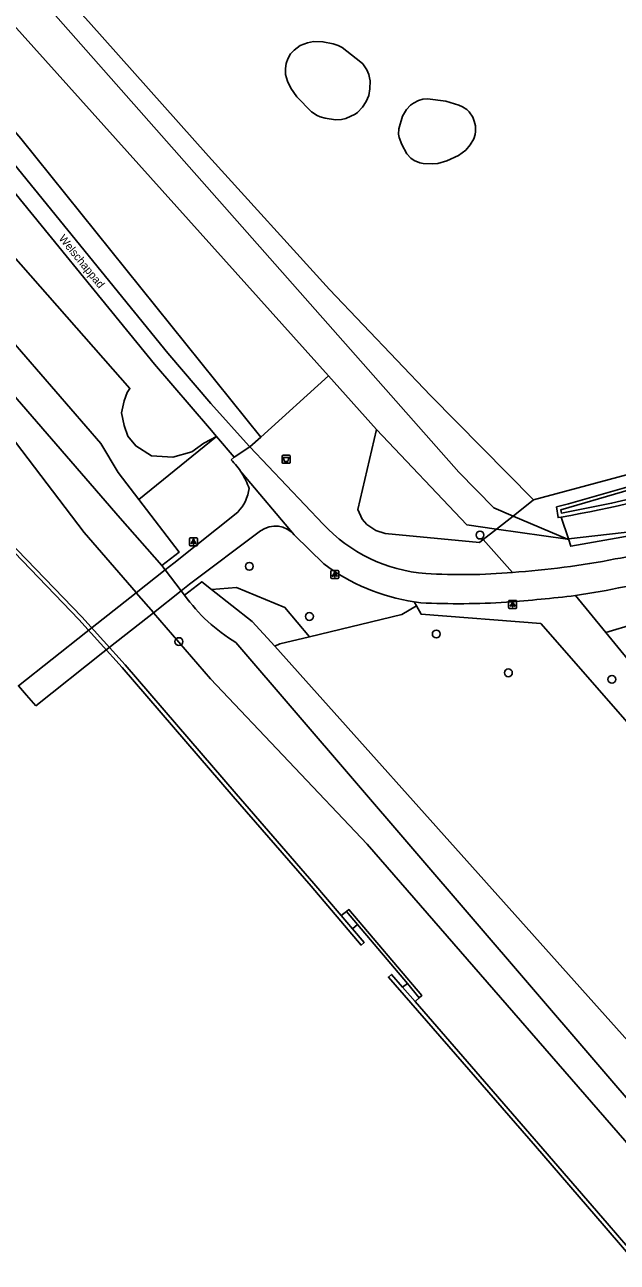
# Model space of a CAD drawing. Extents: x 156061 to 157804, y 383451 to 385640.
# Drawn here: x 157335.7 to 157409.7, y 383817.8 to 383972.4 of the extents above; entities that cross this region are included whole.
import ezdxf

# ---------------------------------------------------------------- set-up
doc = ezdxf.new("R2010")
doc.units = 0
for name, color, linetype in [('IMGEO_Afvalbak', 7, 'Continuous'), ('IMGEO_Berm_groen', 7, 'Continuous'), ('IMGEO_Boom', 7, 'Continuous'), ('IMGEO_Dek', 7, 'Continuous'), ('IMGEO_Fietspad_gesloten', 7, 'Continuous'), ('IMGEO_Fietspad_halfverhard', 7, 'Continuous'), ('IMGEO_Gemengd_bos', 7, 'Continuous'), ('IMGEO_Grasland_overig', 7, 'Continuous'), ('IMGEO_Groenvoorziening', 7, 'Continuous'), ('IMGEO_Hek', 7, 'Continuous'), ('IMGEO_Kademuur', 7, 'Continuous'), ('IMGEO_Lichtpunt', 7, 'Continuous'), ('IMGEO_Loofbos', 7, 'Continuous'), ('IMGEO_Openbare_ruimte_label', 7, 'Continuous'), ('IMGEO_Waterloop', 7, 'Continuous')]:
    doc.layers.add(name, color=color, linetype=linetype)

msp = doc.modelspace()

# ---------------------------------------------------------------- linework, layer by layer
at = {"layer": 'IMGEO_Afvalbak'}
for p, q in [((157367.87, 383917.72), (157367.87, 383918.52)), ((157367.87, 383918.52), (157367.87, 383917.72)), ((157367.97, 383918.62), (157368.76, 383918.62)), ((157368.76, 383918.62), (157367.97, 383918.62)), ((157368.76, 383917.62), (157367.97, 383917.62)), ((157367.97, 383917.62), (157368.76, 383917.62)), ((157368.86, 383918.52), (157368.86, 383917.72)), ((157368.86, 383917.72), (157368.86, 383918.52))]:
    msp.add_line(p, q, dxfattribs=at)
msp.add_lwpolyline([(157368.01, 383918.34), (157368.72, 383918.34), (157368.57, 383917.86), (157368.16, 383917.86), (157368.01, 383918.34)], dxfattribs=at)
for centre, start, end in [((157367.97, 383918.52), 90, 180), ((157367.97, 383918.52), 90, 180), ((157367.97, 383917.72), 180, 270), ((157367.97, 383917.72), 180, 270), ((157368.76, 383918.52), 0, 90), ((157368.76, 383918.52), 360, 90), ((157368.76, 383917.72), 270, 0), ((157368.76, 383917.72), 270, 0)]:
    msp.add_arc(centre, 0.1, start, end, dxfattribs=at)
at = {"layer": 'IMGEO_Berm_groen'}
for points in [[(157359.67, 383920.98), (157358.1, 383920.12), (157356.58, 383919.05), (157354.21, 383918.37), (157351.57, 383918.55), (157349.58, 383919.8), (157348.59, 383921.01), (157348.13, 383922.34), (157347.8, 383923.91), (157348.15, 383925.44), (157348.5, 383926.48), (157348.86, 383926.97), (157290.11, 383993.81)], [(157404.49, 383901.1), (157408.28, 383896.48)], [(157408.28, 383896.48), (157411.9, 383897.54)]]:
    msp.add_lwpolyline(points, dxfattribs=at)
at = {"layer": 'IMGEO_Boom'}
for centre in [(157392.58, 383908.65), (157363.77, 383904.75), (157371.28, 383898.48), (157387.12, 383896.29), (157354.98, 383895.34), (157396.13, 383891.44), (157409.05, 383890.62)]:
    msp.add_circle(centre, 0.489, dxfattribs=at)
at = {"layer": 'IMGEO_Dek'}
msp.add_lwpolyline([(157337.1, 383887.33), (157345.5, 383893.97), (157351.81, 383898.95), (157355.26, 383901.69), (157353.28, 383904.31), (157349.65, 383901.45), (157343.34, 383896.46), (157334.93, 383889.83), (157335.95, 383888.66)], close=True, dxfattribs=at)
at = {"layer": 'IMGEO_Fietspad_gesloten'}
for points in [[(157361.89, 383918.4), (157363.83, 383919.68)], [(157372.99, 383910.03), (157363.83, 383919.68)], [(157361.89, 383918.4), (157361.49, 383918.05)], [(157362.83, 383916.41), (157369.39, 383908.68), (157369.41, 383908.65)], [(157362.33, 383911.52), (157354.33, 383905.13), (157353.28, 383904.31)], [(157355.26, 383901.69), (157356.3, 383902.51), (157365.18, 383909.17)], [(157369.41, 383908.65), (157373.09, 383905.05)], [(157353.28, 383904.31), (157355.26, 383901.69)], [(157384.36, 383900.3), (157385.21, 383900.19)]]:
    msp.add_lwpolyline(points, dxfattribs=at)
for centre, radius, start, end in [((157355.53, 383911.82), 8.62, 32.1357, 46.2952), ((157355.49, 383911.78), 8.68, 18.1348, 32.1986), ((157358.6, 383915.12), 5.18, 316.0682, 352.9886), ((157387.3, 383923.33), 19.54, 222.8896, 265.5902), ((157367.02, 383906.68), 3.09, 39.3452, 126.5048), ((157395.45, 383986.55), 82.09, 279.8246, 287.2036), ((157389.64, 384006.87), 103.13, 273.892, 281.0783), ((157388.1, 383924.92), 24.9, 232.922, 261.3694), ((157390.32, 383981.53), 77.82, 266.6717, 274.6602), ((157386.75, 384018.34), 118.58, 278.604, 284.6469), ((157383.21, 384078.23), 178.41, 274.0796, 276.8514), ((157389.88, 383988.67), 88.6, 266.974, 273.894)]:
    msp.add_arc(centre, radius, start, end, dxfattribs=at)
at = {"layer": 'IMGEO_Fietspad_halfverhard'}
for points in [[(157237.28, 384056.66), (157244.45, 384048.49), (157247.83, 384044.71), (157258.97, 384032.48), (157270.57, 384020.69), (157270.96, 384020.29), (157290.75, 384000.1), (157290.84, 384000), (157295.59, 383994.9), (157306.48, 383982.75), (157317.9, 383970.66), (157322.77, 383965.41), (157327.3, 383960.08), (157331.11, 383955.48), (157351.93, 383929.99), (157358.8, 383922.02), (157359.67, 383920.98)], [(157363.83, 383919.68), (157363.76, 383919.76), (157358.97, 383925.08), (157353.6, 383931.38), (157332.79, 383957.01), (157329.26, 383961.31)], [(157359.67, 383920.98), (157361.89, 383918.4)]]:
    msp.add_lwpolyline(points, dxfattribs=at)
at = {"layer": 'IMGEO_Gemengd_bos'}
for points in [[(157359.67, 383920.98), (157349.99, 383913.1)], [(157352.86, 383904.86), (157353.28, 383904.31)]]:
    msp.add_lwpolyline(points, dxfattribs=at)
at = {"layer": 'IMGEO_Grasland_overig'}
msp.add_lwpolyline([(157365.2, 383920.9), (157363.83, 383919.68)], dxfattribs=at)
at = {"layer": 'IMGEO_Groenvoorziening'}
for points in [[(157369.37, 383969.23), (157368.9, 383968.79), (157368.58, 383968.18), (157368.39, 383967.59), (157368.28, 383966.95), (157368.31, 383966.21), (157368.54, 383965.37), (157368.96, 383964.49), (157369.7, 383963.43), (157371.52, 383961.55), (157372.26, 383961.09), (157372.63, 383960.92), (157373.25, 383960.73), (157374.54, 383960.54), (157375.27, 383960.59), (157375.81, 383960.72), (157376.99, 383961.25), (157377.28, 383961.45), (157377.89, 383962.1), (157378.36, 383962.83), (157378.68, 383963.56), (157378.83, 383964.4), (157378.85, 383965.41), (157378.8, 383965.8), (157378.71, 383966.2), (157378.46, 383966.79), (157377.95, 383967.52), (157377.7, 383967.76), (157375.37, 383969.57), (157374.85, 383969.83), (157374.24, 383970.05), (157372.97, 383970.3), (157371.8, 383970.31), (157371.03, 383970.18), (157370.14, 383969.82), (157369.37, 383969.23)], [(157382.9, 383960.98), (157382.43, 383959.4), (157382.4, 383958.76), (157382.47, 383958.31), (157382.82, 383957.45), (157383.46, 383956.28), (157383.94, 383955.74), (157384.36, 383955.44), (157385.06, 383955.17), (157385.5, 383955.08), (157386.65, 383955.02), (157387.3, 383955.08), (157388.46, 383955.41), (157389.89, 383956.06), (157390.8, 383956.76), (157391.37, 383957.41), (157391.8, 383958.18), (157391.96, 383958.7), (157392.02, 383959.08), (157392.02, 383959.8), (157391.87, 383960.39), (157391.67, 383960.85), (157391.23, 383961.53), (157390.93, 383961.81), (157390.38, 383962.17), (157389.94, 383962.38), (157388.3, 383962.88), (157386.02, 383963.16), (157385.44, 383963.1), (157384.9, 383962.95), (157384.28, 383962.63), (157383.91, 383962.36), (157383.41, 383961.84), (157382.9, 383960.98)], [(157519.27, 383957.9), (157500, 383950.08), (157447.61, 383928.82), (157423.1, 383919.46), (157399.25, 383913.04)], [(157379.67, 383921.83), (157373.67, 383928.53)], [(157402.15, 383912.17), (157402.34, 383910.83), (157402.73, 383910.9)], [(157396.64, 383903.98), (157392.99, 383908.08)], [(157403.62, 383908.16), (157403.49, 383908.15)], [(157355.68, 383901.13), (157355.26, 383901.69)]]:
    msp.add_lwpolyline(points, dxfattribs=at)
msp.add_arc((157316.53, 384234.61), 333.61, 284.8717, 293.1943, dxfattribs=at)
at = {"layer": 'IMGEO_Hek'}
for points in [[(157286.32, 384037.05), (157293.19, 384028.12), (157297.01, 384023.54), (157304.07, 384015.72), (157311.43, 384008.18), (157319.02, 384000), (157343.68, 383972.81), (157358.66, 383956.01), (157373.77, 383939.34), (157386.41, 383926.07), (157399.25, 383913.04)], [(157353.28, 383904.31), (157349.65, 383901.45)], [(157354.33, 383905.13), (157353.28, 383904.31)], [(157355.26, 383901.69), (157356.3, 383902.51)], [(157343.34, 383896.46), (157349.65, 383901.45)], [(157351.81, 383898.95), (157355.26, 383901.69)], [(157351.81, 383898.95), (157345.5, 383893.97)], [(157334.93, 383889.83), (157343.34, 383896.46)], [(157345.5, 383893.97), (157337.1, 383887.33)]]:
    msp.add_lwpolyline(points, dxfattribs=at)
at = {"layer": 'IMGEO_Kademuur'}
for points in [[(157376.67, 383859.44), (157378.11, 383857.74), (157377.73, 383857.42), (157371.48, 383864.77), (157361.75, 383875.99), (157355.83, 383882.85), (157347.9, 383892.1), (157342.5, 383898.09), (157334.43, 383906.47), (157325.55, 383916.1), (157309.5, 383934.38), (157294.52, 383951.52), (157282.86, 383964.9), (157280.49, 383967.59), (157272.31, 383977.07), (157264.58, 383985.94), (157253.91, 383998.21), (157241.38, 384012.46), (157224.89, 384031.26), (157207.53, 384051.62), (157207.91, 384051.95), (157209.47, 384050.11)], [(157375.25, 383861.1), (157371.85, 383865.1), (157362.13, 383876.31), (157356.21, 383883.18), (157348.28, 383892.43), (157342.87, 383898.43), (157334.79, 383906.81), (157325.92, 383916.44), (157309.88, 383934.71), (157294.9, 383951.85), (157283.23, 383965.23), (157280.87, 383967.92), (157272.69, 383977.4), (157264.96, 383986.27), (157262.91, 383988.62)], [(157375.25, 383861.1), (157376.67, 383859.44)], [(157384.99, 383850.84), (157385.3, 383851.1), (157376.22, 383861.86), (157375.91, 383861.6)], [(157375.91, 383861.6), (157377.27, 383859.99)], [(157383.51, 383852.6), (157377.27, 383859.99)], [(157433.96, 383793.13), (157433.58, 383792.81), (157425.95, 383801.7), (157410.64, 383819.38), (157408.07, 383822.35), (157399.52, 383832.27), (157389.52, 383843.8), (157381.15, 383853.41), (157381.52, 383853.74), (157382.9, 383852.15)], [(157384.48, 383850.35), (157382.9, 383852.15)], [(157383.51, 383852.6), (157384.99, 383850.84)], [(157411.06, 383819.66), (157408.45, 383822.68), (157399.89, 383832.6), (157389.9, 383844.13), (157384.48, 383850.35)]]:
    msp.add_lwpolyline(points, dxfattribs=at)
at = {"layer": 'IMGEO_Lichtpunt'}
for p, q in [((157356.3, 383908.21), (157356.3, 383907.4)), ((157356.3, 383908.21), (157356.3, 383907.4)), ((157357.2, 383908.31), (157356.4, 383908.31)), ((157357.2, 383908.31), (157356.4, 383908.31)), ((157356.4, 383907.31), (157357.2, 383907.31)), ((157356.4, 383907.31), (157357.2, 383907.31)), ((157357.3, 383907.4), (157357.3, 383908.21)), ((157357.3, 383907.4), (157357.3, 383908.21)), ((157373.95, 383904.12), (157373.95, 383903.32)), ((157373.95, 383904.12), (157373.95, 383903.32)), ((157374.85, 383904.22), (157374.05, 383904.22)), ((157374.85, 383904.22), (157374.05, 383904.22)), ((157374.95, 383903.32), (157374.95, 383904.12)), ((157374.95, 383903.32), (157374.95, 383904.12)), ((157374.05, 383903.22), (157374.85, 383903.22)), ((157374.05, 383903.22), (157374.85, 383903.22)), ((157396.16, 383900.39), (157396.16, 383899.58)), ((157396.16, 383900.39), (157396.16, 383899.58)), ((157397.06, 383900.49), (157396.26, 383900.49)), ((157397.06, 383900.49), (157396.26, 383900.49)), ((157396.26, 383899.49), (157397.06, 383899.49)), ((157396.26, 383899.49), (157397.06, 383899.49)), ((157397.16, 383899.58), (157397.16, 383900.39)), ((157397.16, 383899.58), (157397.16, 383900.39))]:
    msp.add_line(p, q, dxfattribs=at)
for points in [[(157356.68, 383907.87), (157356.71, 383907.85), (157356.53, 383907.58), (157356.49, 383907.61), (157356.68, 383907.87)], [(157356.78, 383907.83), (157356.83, 383907.83), (157356.83, 383907.5), (157356.78, 383907.5), (157356.78, 383907.83)], [(157356.89, 383907.85), (157356.93, 383907.87), (157357.11, 383907.61), (157357.07, 383907.58), (157356.89, 383907.85)], [(157374.33, 383903.79), (157374.36, 383903.76), (157374.18, 383903.5), (157374.14, 383903.52), (157374.33, 383903.79)], [(157374.43, 383903.74), (157374.47, 383903.74), (157374.47, 383903.42), (157374.43, 383903.42), (157374.43, 383903.74)], [(157374.54, 383903.76), (157374.58, 383903.79), (157374.76, 383903.52), (157374.72, 383903.5), (157374.54, 383903.76)], [(157396.54, 383900.05), (157396.57, 383900.03), (157396.39, 383899.76), (157396.35, 383899.79), (157396.54, 383900.05)], [(157396.64, 383900.01), (157396.68, 383900.01), (157396.68, 383899.68), (157396.64, 383899.68), (157396.64, 383900.01)], [(157396.75, 383900.03), (157396.79, 383900.05), (157396.97, 383899.79), (157396.93, 383899.76), (157396.75, 383900.03)]]:
    msp.add_lwpolyline(points, dxfattribs=at)
for centre in [(157356.8, 383908.01), (157374.45, 383903.92), (157396.66, 383900.19)]:
    msp.add_circle(centre, 0.0994, dxfattribs=at)
for centre, start, end in [((157356.4, 383908.21), 90, 180), ((157356.4, 383908.21), 90, 180), ((157356.4, 383907.4), 180, 270), ((157356.4, 383907.4), 180, 270), ((157357.2, 383908.21), 0, 90), ((157357.2, 383908.21), 0, 90), ((157357.2, 383907.4), 270, 0), ((157357.2, 383907.4), 270, 360), ((157374.05, 383904.12), 90, 180), ((157374.05, 383904.12), 90, 180), ((157374.85, 383904.12), 0, 90), ((157374.85, 383904.12), 0, 90), ((157374.05, 383903.32), 180, 270), ((157374.05, 383903.32), 180, 270), ((157374.85, 383903.32), 270, 0), ((157374.85, 383903.32), 270, 360), ((157396.26, 383900.39), 90, 180), ((157396.26, 383900.39), 90, 180), ((157396.26, 383899.58), 180, 270), ((157396.26, 383899.58), 180, 270), ((157397.06, 383900.39), 0, 90), ((157397.06, 383900.39), 0, 90), ((157397.06, 383899.58), 270, 0), ((157397.06, 383899.58), 270, 360)]:
    msp.add_arc(centre, 0.0946, start, end, dxfattribs=at)
at = {"layer": 'IMGEO_Loofbos'}
for points in [[(157365.2, 383920.9), (157335.25, 383958.19), (157331.44, 383962.58), (157296.37, 384001.71), (157240.49, 384061.73), (157146.72, 384164.63), (157070.21, 384252.24), (157021.33, 384305.5), (157019.79, 384303.65)], [(157399.25, 383913.04), (157386.41, 383926.07), (157373.77, 383939.34), (157358.66, 383956.01), (157343.68, 383972.81), (157319.02, 384000), (157311.43, 384008.18), (157304.07, 384015.72), (157297.01, 384023.54), (157293.19, 384028.12), (157286.32, 384037.05)], [(157288.58, 384031.37), (157316.26, 384000), (157389.92, 383916.52), (157394.32, 383912.05), (157396.72, 383911.03)], [(157254.44, 384012.4), (157256.7, 384009.01), (157257.6, 384007.87), (157258.64, 384006.72), (157266.08, 384000), (157268.9, 383997.1), (157270.88, 383994.91), (157273.88, 383991.3), (157276.33, 383988.04), (157301.53, 383958.34), (157326.74, 383930.52), (157343.16, 383908.98), (157349.65, 383901.46), (157349.65, 383901.45), (157351.8, 383898.96), (157351.81, 383898.95), (157358.93, 383890.7), (157378.47, 383870.02), (157418.16, 383824.39)], [(157349.99, 383913.1), (157347.41, 383916.46), (157345.22, 383920.11), (157330.2, 383937.44), (157307.42, 383964.66), (157281.28, 383994.6)], [(157276.22, 383992.1), (157300.44, 383965.27), (157347.66, 383910.77), (157352.86, 383904.86)], [(157373.67, 383928.53), (157333.94, 383972.83), (157321.57, 383986.86)], [(157373.67, 383928.53), (157365.2, 383920.9)], [(157379.67, 383921.83), (157377.31, 383911.85), (157377.88, 383910.65), (157378.46, 383909.97), (157379.56, 383909.21), (157380.72, 383908.85), (157392.53, 383907.71), (157392.99, 383908.08)], [(157394.65, 383909.39), (157390.94, 383909.91), (157379.67, 383921.83)], [(157349.99, 383913.1), (157355.03, 383906.53), (157352.86, 383904.86)], [(157396.72, 383911.03), (157399.25, 383913.04)], [(157396.72, 383911.03), (157394.65, 383909.39)], [(157403.49, 383908.15), (157396.72, 383911.03)], [(157402.73, 383910.9), (157403.62, 383908.16)], [(157392.99, 383908.08), (157394.65, 383909.39)], [(157394.65, 383909.39), (157403.49, 383908.15)], [(157403.62, 383908.16), (157417.15, 383909.72)], [(157417.15, 383909.72), (157416.42, 383909.48), (157403.92, 383907.26), (157403.62, 383908.16)], [(157359.06, 383901.85), (157357.85, 383902.81), (157355.68, 383901.13)], [(157371.27, 383895.95), (157368.21, 383899.58), (157362.19, 383902.09), (157359.06, 383901.85)], [(157359.06, 383901.85), (157364.11, 383897.84), (157366.96, 383894.75)], [(157384.66, 383899.79), (157382.82, 383898.73), (157371.27, 383895.95)], [(157384.36, 383900.3), (157384.66, 383899.79)], [(157431.48, 383827.17), (157426.55, 383832.92), (157448.35, 383842.52), (157400.16, 383897.58), (157385.25, 383898.76), (157384.66, 383899.79)], [(157371.27, 383895.95), (157367.6, 383895.07), (157366.96, 383894.75)], [(157436.99, 383829.44), (157434.93, 383831.83), (157454.23, 383840.38), (157408.28, 383896.48)], [(157421.11, 383826.36), (157362.08, 383895.23)], [(157366.96, 383894.75), (157425.49, 383829.27)], [(157375.91, 383861.6), (157375.25, 383861.1)], [(157384.48, 383850.35), (157384.99, 383850.84)]]:
    msp.add_lwpolyline(points, dxfattribs=at)
for centre, radius, start, end in [((157374.47, 384071.97), 163.53, 279.9504, 286.7311), ((157373.14, 383913.64), 21.47, 215.6319, 239.0229)]:
    msp.add_arc(centre, radius, start, end, dxfattribs=at)
at = {"layer": 'IMGEO_Waterloop'}
for points in [[(157415.25, 383914.11), (157409.02, 383912.63), (157402.75, 383911.4), (157402.69, 383911.82), (157418.07, 383916.32)], [(157377.27, 383859.99), (157376.67, 383859.44)], [(157382.9, 383852.15), (157383.51, 383852.6)]]:
    msp.add_lwpolyline(points, dxfattribs=at)

# ---------------------------------------------------------------- texts
at = {"layer": 'IMGEO_Openbare_ruimte_label'}
msp.add_text('Welschappad', height=1, rotation=309.1161, dxfattribs=at).set_placement((157339.91, 383945.68))

doc.saveas('drawing.dxf')
